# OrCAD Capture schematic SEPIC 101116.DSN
size C
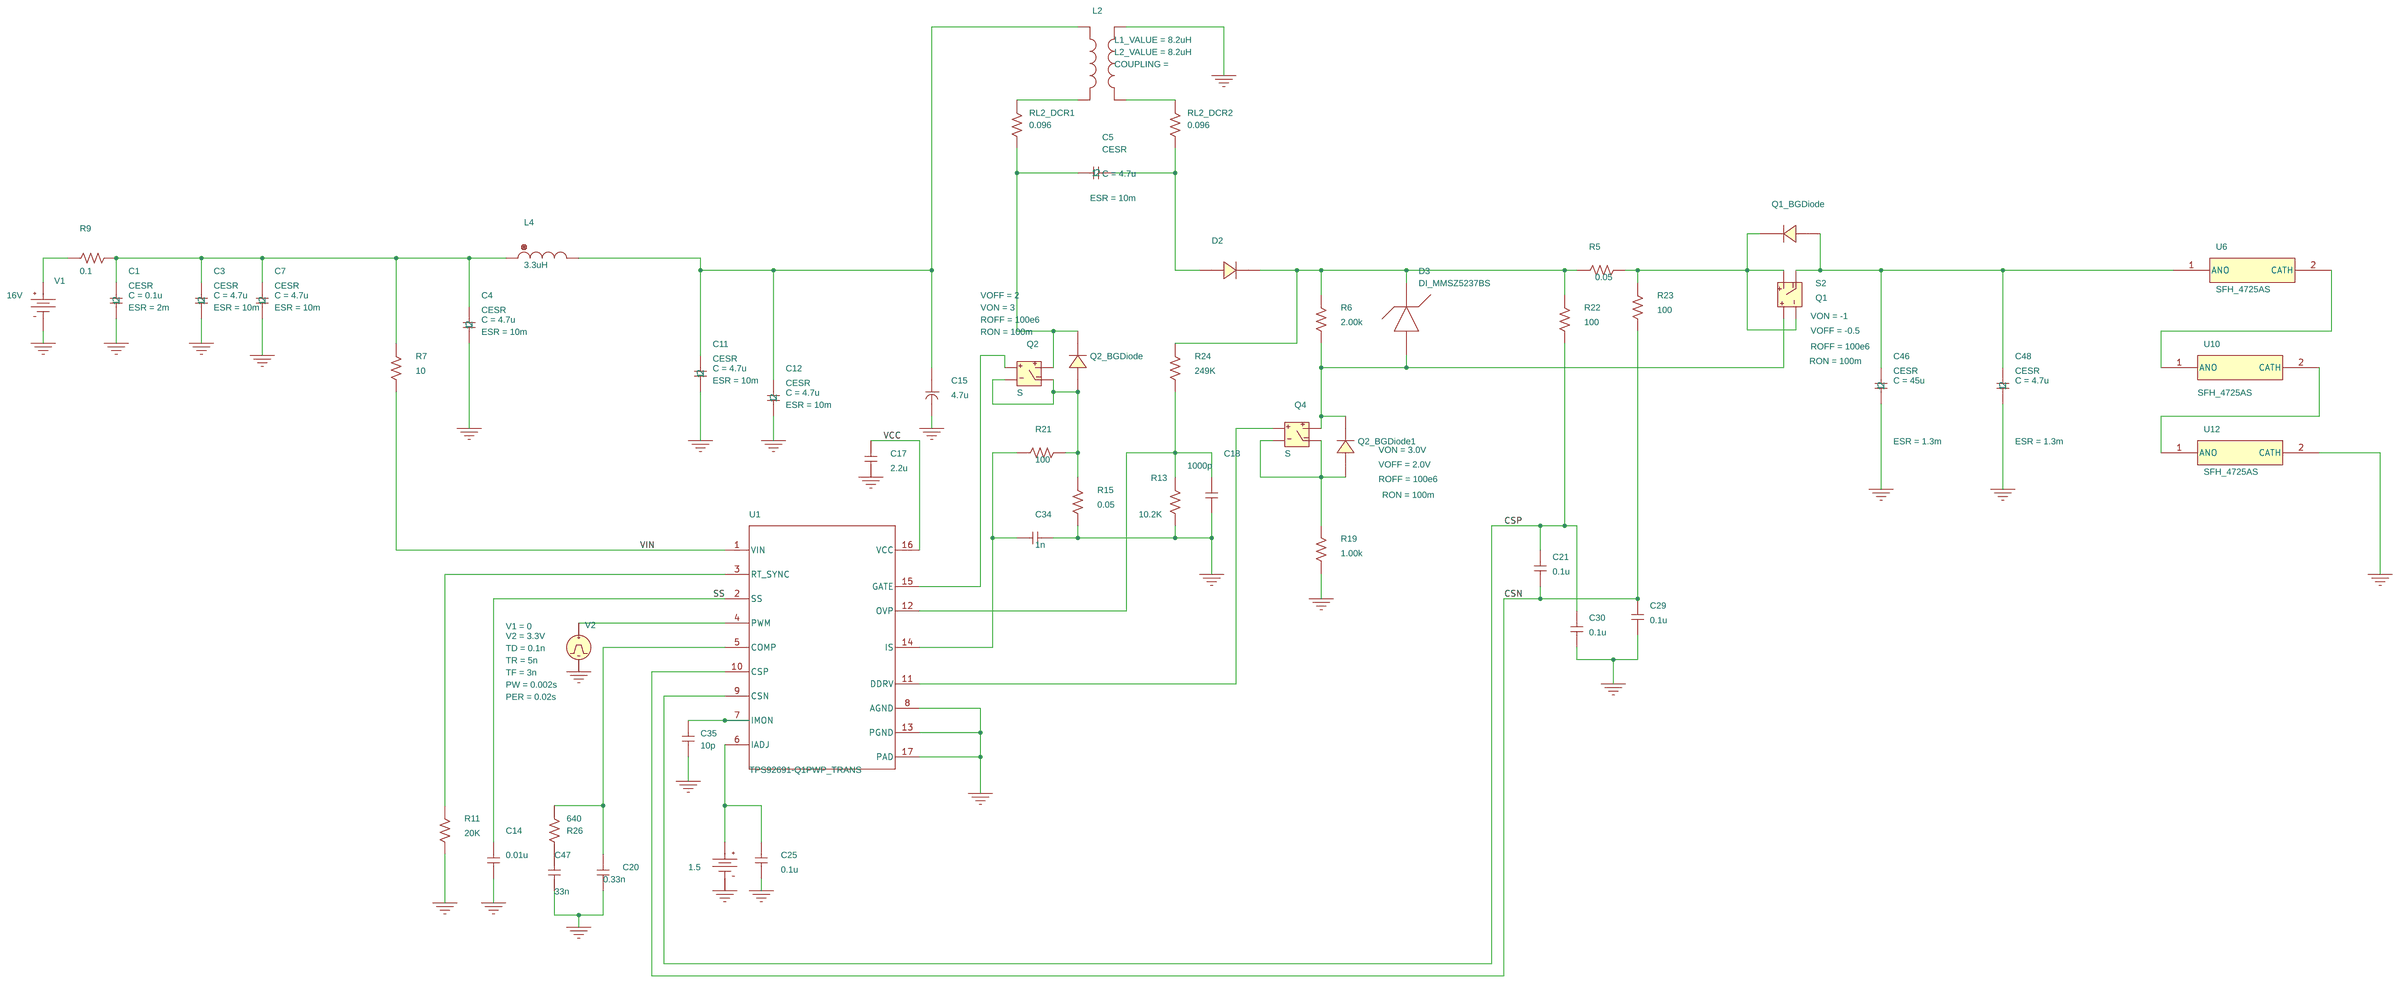
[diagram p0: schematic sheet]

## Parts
C1  CESR
C3  CESR
C4  CESR
C5  CESR
C7  CESR
C11  CESR
C12  CESR
C14  0.01u  [RAD/CK05]
C15  4.7u  [DIPCAP]
C17  2.2u  [RAD/CK05]
C18  1000p  [RAD/CK05]
C20  0.33n  [RAD/CK05]
C21  0.1u  [RAD/CK05]
C25  0.1u  [RAD/CK05]
C29  0.1u  [RAD/CK05]
C30  0.1u  [RAD/CK05]
C34  1n  [RAD/CK05]
C35  10p  [RAD/CK05]
C46  CESR
C47  33n  [RAD/CK05]
C48  CESR
D2  D_D1
D3  DI_MMSZ5237BS
L2  XFRM_LINEAR
L4  3.3uH  [DISC/.350x.175/LS.200x.100/.034]
Q1_BGDiode  Q1_BGDiode
Q2  S
Q2_BGDiode  Q2_BGDiode
Q2_BGDiode1  Q2_BGDiode
Q4  S
R5  0.05  [AX/RC05]
R6  2.00k  [AX/RC05]
R7  10  [AX/RC05]
R9  0.1  [AX/RC05]
R11  20K  [AX/RC05]
R13  10.2K  [AX/RC05]
R15  0.05  [AX/RC05]
R19  1.00k  [AX/RC05]
R21  100  [AX/RC05]
R22  100  [AX/RC05]
R23  100  [AX/RC05]
R24  249K  [AX/RC05]
R26  640  [AX/RC05]
RL2_DCR1  0.096  [AX/RC05]
RL2_DCR2  0.096  [AX/RC05]
S2  Q1
U1  TPS92691-Q1PWP_TRANS  [PWP0016J_N]
U6  SFH_4725AS
U10  SFH_4725AS
U12  SFH_4725AS
V1  VDC
V2  VPULSE
VIDJ  VDC

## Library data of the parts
C1 = CESR_0_2: C: 0.1u; ESR: 2m; PSpiceTemplate: X^@REFDES %1 %2 @MODEL PARAMS: ?C|C=@C||C=10U| ?ESR|ESR=@ESR||ESR=2M|
C3 = CESR_0_4: C: 4.7u; ESR: 10m; PSpiceTemplate: X^@REFDES %1 %2 @MODEL PARAMS: ?C|C=@C||C=10U| ?ESR|ESR=@ESR||ESR=2M|
C4 = CESR_0_5: C: 4.7u; ESR: 10m; PSpiceTemplate: X^@REFDES %1 %2 @MODEL PARAMS: ?C|C=@C||C=10U| ?ESR|ESR=@ESR||ESR=2M|
C5 = CESR_0_8: C: 4.7u; ESR: 10m; PSpiceTemplate: X^@REFDES %1 %2 @MODEL PARAMS: ?C|C=@C||C=10U| ?ESR|ESR=@ESR||ESR=2M|
C7 = CESR_0: C: 4.7u; ESR: 10m; PSpiceTemplate: X^@REFDES %1 %2 @MODEL PARAMS: ?C|C=@C||C=10U| ?ESR|ESR=@ESR||ESR=2M|
C11 = CESR_0_3: C: 4.7u; ESR: 10m; PSpiceTemplate: X^@REFDES %1 %2 @MODEL PARAMS: ?C|C=@C||C=10U| ?ESR|ESR=@ESR||ESR=2M|
C12 = CESR_0_6: C: 4.7u; ESR: 10m; PSpiceTemplate: X^@REFDES %1 %2 @MODEL PARAMS: ?C|C=@C||C=10U| ?ESR|ESR=@ESR||ESR=2M|
C14 C17 C18 C20 C21 C25 C29 C30 C34 C35 C47 = C
C15 = CAPACITOR
C46 = CESR_0_7: C: 45u; ESR: 1.3m; PSpiceTemplate: X^@REFDES %1 %2 @MODEL PARAMS: ?C|C=@C||C=10U| ?ESR|ESR=@ESR||ESR=2M|
C48 = CESR_0_1: C: 4.7u; ESR: 1.3m; PSpiceTemplate: X^@REFDES %1 %2 @MODEL PARAMS: ?C|C=@C||C=10U| ?ESR|ESR=@ESR||ESR=2M|
D2 Q1_BGDiode Q2_BGDiode Q2_BGDiode1 = D_D1
D3 = DI_MMSZ5237BS: PSpiceTemplate: X^@REFDES %1 %2 @MODEL
L2 = XFRM_LINEAR: L1_VALUE: 8.2uH; L2_VALUE: 8.2uH
L4 = L
Q2 = S: ROFF: 100e6; RON: 100m; VOFF: 2; VON: 3
Q4 = S: ROFF: 100e6; RON: 100m; VOFF: 2.0V; VON: 3.0V
R5-R7 R9 R11 R13 R15 R19 R21-R24 R26 RL2_DCR1 RL2_DCR2 = R
S2 = S: ROFF: 100e6; RON: 100m; VOFF: -0.5; VON: -1
U1 = TPS92691-Q1PWP_TRANS
U6 U10 U12 = SFH_4725AS
V1 = VDC: DC: 16V
V2 = VPULSE: PER: 0.02s; PW: 0.002s; TD: 0.1n; TF: 3n; TR: 5n; V1: 0; V2: 3.3V
VIDJ = VDC: DC: 1.5

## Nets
VCC: C17.1 U1.16(VCC)
VIN: R7.2 U1.1(VIN)
0: C1.1 C3.1 C4.1 C7.1 C11.1 C12.1 C14.2 C15.2(B) C17.2 C18.2 C20.2 C25.2 C29.2 C30.2 C34.2 C35.2 C46.1 C47.2 C48.1 L2.3 R11.2 R13.2 R15.2 R19.1 U1.8(AGND) U1.13(PGND) U1.17(PAD) U12.2(CATH) V1.1(-) V2.2(-) VIDJ.1(-)
CSN: C21.2 C29.1 R23.2 U1.10(CSP)
CSP: C21.1 C30.1 R22.2 U1.9(CSN)
SS: C14.1 U1.2(SS)
N155551: C11.2 C12.2 C15.1(A) L2.1 L4.2
N155573: C18.1 R13.1 R24.2 U1.12(OVP)
N155599: D3.1 Q2_BGDiode1.2 Q4.2(3) R6.2 S2.0(1)
N155607: Q2_BGDiode1.1 Q4.1(2) Q4.3(4) R19.2
N155649: C46.2 C48.2 Q1_BGDiode.1 S2.3(4) U6.1(ANO)
N155653: Q1_BGDiode.2 R5.2 R23.1 S2.1(2) S2.2(3)
N155801: U10.2(CATH) U12.1(ANO)
N155811: Q2.1(2) Q2.3(4) Q2_BGDiode.1 R15.1 R21.2
N155851: C34.1 R21.1 U1.14(IS)
N156181: D2.2 D3.2 R5.1 R6.1 R22.1 R24.1
N156415: C1.2 C3.2 C4.2 C7.2 L4.1 R7.1 R9.2
N156419: C35.1 U1.7(IMON)
N156551: R9.1 V1.0(+)
N156581: C20.1 R26.1 U1.5(COMP)
N156683: R11.1 U1.3(RT_SYNC)
N156939: C5.1 Q2.2(3) Q2_BGDiode.2 RL2_DCR1.2
N157119: U6.2(CATH) U10.1(ANO)
N157183: Q2.0(1) U1.15(GATE)
N157439: Q4.0(1) U1.11(DDRV)
N157841: C25.1 U1.6(IADJ) VIDJ.0(+)
N158513: L2.2 RL2_DCR1.1
N158517: L2.4 RL2_DCR2.1
N158521: C5.2 D2.1 RL2_DCR2.2
N193079: U1.4(PWM) V2.1(+)
N213251: C47.1 R26.2
